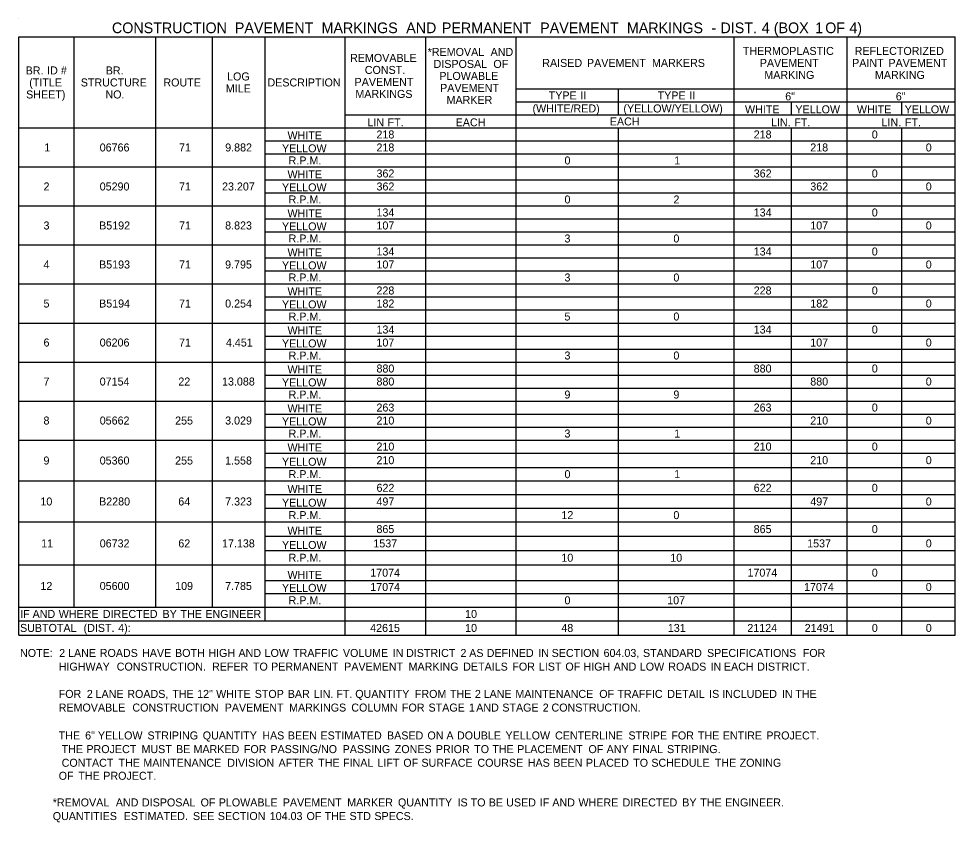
# Model space of a CAD drawing. Extents: x 544420 to 1930787, y -1947044 to 596640.
# Drawn here: x 548031 to 548733, y -1946708 to -1946106 of the extents above; entities that cross this region are included whole.
import ezdxf

# ---------------------------------------------------------------- set-up
doc = ezdxf.new("R2010")
doc.units = 0
doc.layers.add('Default', color=7, linetype='Continuous')

msp = doc.modelspace()

# ---------------------------------------------------------------- linework, layer by layer
at = {"layer": 'Default'}
for p, q in [((548030.53, -1946105.71), (548030.53, -1946105.71)), ((548030.53, -1946119.36), (548732.53, -1946119.36)), ((548030.53, -1946119.36), (548335.71, -1946119.36)), ((548030.53, -1946567.86), (548030.53, -1946119.36)), ((548071.97, -1946546.9), (548071.97, -1946119.36)), ((548133.39, -1946546.9), (548133.39, -1946119.36)), ((548175.81, -1946546.9), (548175.81, -1946119.36)), ((548215.29, -1946557.14), (548215.29, -1946119.36)), ((548275.26, -1946567.86), (548275.26, -1946119.36)), ((548335.71, -1946567.86), (548335.71, -1946119.36)), ((548403.47, -1946567.86), (548403.47, -1946119.36)), ((548566.78, -1946567.86), (548566.78, -1946119.36)), ((548651.61, -1946187.61), (548651.61, -1946119.36)), ((548651.61, -1946567.86), (548651.61, -1946119.36)), ((548732.53, -1946567.86), (548732.53, -1946119.36)), ((548403.47, -1946158.36), (548732.53, -1946158.36)), ((548480.01, -1946177.86), (548480.01, -1946158.36)), ((548403.47, -1946168.11), (548732.53, -1946168.11)), ((548609.68, -1946177.86), (548609.68, -1946168.11)), ((548692.56, -1946177.86), (548692.56, -1946168.11)), ((548275.26, -1946177.86), (548732.53, -1946177.86)), ((548275.26, -1946187.61), (548275.26, -1946177.86)), ((548335.71, -1946187.61), (548335.71, -1946177.86)), ((548403.47, -1946187.61), (548403.47, -1946177.86)), ((548030.53, -1946187.61), (548215.29, -1946187.61)), ((548030.53, -1946187.61), (548175.81, -1946187.61)), ((548175.81, -1946187.61), (548732.53, -1946187.61)), ((548480.01, -1946567.86), (548480.01, -1946187.61)), ((548566.78, -1946187.61), (548651.61, -1946187.61)), ((548609.68, -1946567.86), (548609.68, -1946187.61)), ((548651.61, -1946187.61), (548732.53, -1946187.61)), ((548692.56, -1946567.86), (548692.56, -1946187.61)), ((548215.29, -1946197.36), (548732.53, -1946197.36)), ((548215.29, -1946207.11), (548732.53, -1946207.11)), ((548030.53, -1946216.86), (548732.53, -1946216.86)), ((548215.29, -1946226.61), (548732.53, -1946226.61)), ((548215.29, -1946236.36), (548732.53, -1946236.36)), ((548030.53, -1946246.11), (548732.53, -1946246.11)), ((548215.29, -1946255.86), (548732.53, -1946255.86)), ((548215.29, -1946265.61), (548732.53, -1946265.61)), ((548030.53, -1946275.36), (548732.53, -1946275.36)), ((548215.29, -1946285.11), (548732.53, -1946285.11)), ((548215.29, -1946294.86), (548732.53, -1946294.86)), ((548030.53, -1946304.61), (548732.53, -1946304.61)), ((548215.29, -1946314.36), (548732.53, -1946314.36)), ((548215.29, -1946324.11), (548732.53, -1946324.11)), ((548030.53, -1946333.86), (548732.53, -1946333.86)), ((548215.29, -1946343.61), (548732.53, -1946343.61)), ((548215.29, -1946353.36), (548732.53, -1946353.36)), ((548030.53, -1946363.11), (548732.53, -1946363.11)), ((548215.29, -1946372.86), (548732.53, -1946372.86)), ((548215.29, -1946382.61), (548732.53, -1946382.61)), ((548030.53, -1946392.36), (548732.53, -1946392.36)), ((548215.29, -1946402.11), (548732.53, -1946402.11)), ((548215.29, -1946411.86), (548732.53, -1946411.86)), ((548030.53, -1946421.61), (548732.53, -1946421.61)), ((548215.29, -1946431.36), (548732.53, -1946431.36)), ((548215.29, -1946442.09), (548732.53, -1946442.09)), ((548030.53, -1946452.32), (548732.53, -1946452.32)), ((548215.29, -1946462.56), (548732.53, -1946462.56)), ((548215.29, -1946472.8), (548732.53, -1946472.8)), ((548030.53, -1946483.04), (548732.53, -1946483.04)), ((548215.29, -1946493.76), (548732.53, -1946493.76)), ((548215.29, -1946504.49), (548732.53, -1946504.49)), ((548030.53, -1946515.21), (548732.53, -1946515.21)), ((548215.29, -1946526.91), (548732.53, -1946526.91)), ((548215.29, -1946536.66), (548732.53, -1946536.66)), ((548030.53, -1946546.9), (548732.53, -1946546.9)), ((548215.29, -1946557.14), (548215.29, -1946546.9)), ((548335.71, -1946567.86), (548335.71, -1946546.9)), ((548403.47, -1946567.86), (548403.47, -1946546.9)), ((548480.01, -1946567.86), (548480.01, -1946546.9)), ((548566.78, -1946567.86), (548566.78, -1946546.9)), ((548609.68, -1946567.86), (548609.68, -1946546.9)), ((548651.61, -1946567.86), (548651.61, -1946546.9)), ((548692.56, -1946567.86), (548692.56, -1946546.9)), ((548030.53, -1946557.14), (548732.53, -1946557.14)), ((548275.26, -1946567.86), (548275.26, -1946557.14)), ((548030.53, -1946567.86), (548732.53, -1946567.86))]:
    msp.add_line(p, q, dxfattribs=at)

# ---------------------------------------------------------------- texts
for s, height, p in [('CONSTRUCTION', 8, (548100.42, -1946116.54)), (' PAVEMENT', 8, (548189.57, -1946116.54)), (' MARKINGS', 8, (548254.56, -1946116.54)), (' AND', 8, (548317.98, -1946116.54)), (' PERMANENT', 8, (548344.74, -1946116.54)), (' PAVEMENT', 8, (548418.42, -1946116.54)), (' MARKINGS', 8, (548483.41, -1946116.54)), (' DIST.', 8, (548553.57, -1946116.54)), (' 4', 8, (548584.47, -1946116.54)), (' (BOX', 8, (548593.53, -1946116.54)), (' 1', 8, (548624.57, -1946116.54)), (' OF', 8, (548632.07, -1946116.54)), (' 4)', 8, (548650.18, -1946116.54)), (' -', 8, (548546.82, -1946116.54)), ('REMOVABLE', 6, (548278.9, -1946138.11)), ('*REMOVAL', 6, (548337.08, -1946133.61)), (' AND', 6, (548382.01, -1946133.61)), ('THERMOPLASTIC', 6, (548573.31, -1946132.86)), ('REFLECTORIZED', 6, (548657.11, -1946132.86)), ('DISPOSAL', 6, (548341.49, -1946142.61)), (' OF', 6, (548384.1, -1946142.61)), ('RAISED', 6, (548422.97, -1946141.86)), (' PAVEMENT', 6, (548454.23, -1946141.86)), (' MARKERS', 6, (548502.97, -1946141.86)), ('PAVEMENT', 6, (548585.99, -1946141.86)), ('PAINT', 6, (548655.21, -1946141.86)), (' PAVEMENT', 6, (548680.19, -1946141.86)), ('BR.', 6, (548035.73, -1946147.49)), (' ID', 6, (548049.59, -1946147.49)), (' #', 6, (548059.88, -1946147.49)), ('BR.', 6, (548095.75, -1946147.49)), ('LOG', 6, (548186.72, -1946151.99)), ('CONST.', 6, (548289.93, -1946147.11)), ('PLOWABLE', 6, (548345.81, -1946151.61)), ('MARKING', 6, (548589.42, -1946150.86)), ('MARKING', 6, (548672.3, -1946150.86)), ('(TITLE', 6, (548038.42, -1946156.49)), ('STRUCTURE', 6, (548077.04, -1946156.49)), ('ROUTE', 6, (548138.97, -1946156.49)), ('DESCRIPTION', 6, (548216.96, -1946156.49)), ('PAVEMENT', 6, (548282.27, -1946156.11)), ('SHEET)', 6, (548036.09, -1946165.49)), ('NO.', 6, (548095.52, -1946165.49)), ('MILE', 6, (548185.74, -1946160.99)), ('MARKINGS', 6, (548282.86, -1946165.11)), ('PAVEMENT', 6, (548346.38, -1946160.61)), ('TYPE', 6, (548427.78, -1946166.24)), (' II', 6, (548449.26, -1946166.24)), ('TYPE', 6, (548509.43, -1946166.24)), (' II', 6, (548530.92, -1946166.24)), ('6"', 6, (548605.08, -1946166.91)), ('6"', 6, (548687.96, -1946166.91)), ('MARKER', 6, (548351.21, -1946169.61)), ('(WHITE/RED)', 6, (548415.65, -1946175.99)), ('(YELLOW/YELLOW)', 6, (548483.79, -1946175.99)), ('WHITE', 6, (548574.93, -1946176.66)), ('YELLOW', 6, (548612.72, -1946176.66)), ('WHITE', 6, (548658.78, -1946176.66)), ('YELLOW', 6, (548694.62, -1946176.66)), ('LIN', 6, (548291.9, -1946186.41)), (' FT.', 6, (548304.74, -1946186.41)), ('EACH', 6, (548358.03, -1946186.41)), ('EACH', 6, (548473.57, -1946185.74)), ('LIN.', 6, (548594.4, -1946186.41)), (' FT.', 6, (548609.66, -1946186.41)), ('LIN.', 6, (548677.28, -1946186.41)), (' FT.', 6, (548692.53, -1946186.41)), ('218', 6, (548298.68, -1946195.49)), ('218', 6, (548581.43, -1946195.49)), ('0', 6, (548669.95, -1946195.49)), ('WHITE', 6, (548231.99, -1946196.16)), ('1', 6, (548049.69, -1946205.24)), ('06766', 6, (548091.22, -1946205.24)), ('71', 6, (548150.71, -1946205.24)), ('9.882', 6, (548185.29, -1946205.24)), ('YELLOW', 6, (548227.85, -1946205.91)), ('218', 6, (548298.68, -1946205.24)), ('218', 6, (548623.84, -1946205.24)), ('0', 6, (548710.41, -1946205.24)), ('R.P.M.', 6, (548232.83, -1946214.99)), ('0', 6, (548439.61, -1946214.99)), ('1', 6, (548521.83, -1946214.99)), ('WHITE', 6, (548231.99, -1946225.41)), ('362', 6, (548298.71, -1946224.74)), ('362', 6, (548581.46, -1946224.74)), ('0', 6, (548669.95, -1946224.74)), ('2', 6, (548049.14, -1946234.49)), ('05290', 6, (548091.23, -1946234.49)), ('71', 6, (548150.71, -1946234.49)), ('23.207', 6, (548182.93, -1946234.49)), ('YELLOW', 6, (548227.85, -1946235.16)), ('362', 6, (548298.71, -1946234.49)), ('362', 6, (548623.88, -1946234.49)), ('0', 6, (548710.41, -1946234.49)), ('R.P.M.', 6, (548232.83, -1946244.24)), ('0', 6, (548439.61, -1946244.24)), ('2', 6, (548521.29, -1946244.24)), ('WHITE', 6, (548231.99, -1946254.66)), ('134', 6, (548298.69, -1946253.99)), ('134', 6, (548581.44, -1946253.99)), ('0', 6, (548669.95, -1946253.99)), ('3', 6, (548049.11, -1946263.74)), ('B5192', 6, (548090.79, -1946263.74)), ('71', 6, (548150.71, -1946263.74)), ('8.823', 6, (548185.26, -1946263.74)), ('YELLOW', 6, (548227.85, -1946264.41)), ('107', 6, (548298.68, -1946263.74)), ('107', 6, (548623.84, -1946263.74)), ('0', 6, (548710.41, -1946263.74)), ('R.P.M.', 6, (548232.83, -1946273.49)), ('3', 6, (548439.6, -1946273.49)), ('0', 6, (548521.26, -1946273.49)), ('WHITE', 6, (548231.99, -1946283.91)), ('134', 6, (548298.69, -1946283.24)), ('134', 6, (548581.44, -1946283.24)), ('0', 6, (548669.95, -1946283.24)), ('4', 6, (548049.12, -1946292.99)), ('B5193', 6, (548090.75, -1946292.99)), ('71', 6, (548150.71, -1946292.99)), ('9.795', 6, (548185.23, -1946292.99)), ('YELLOW', 6, (548227.85, -1946293.66)), ('107', 6, (548298.68, -1946292.99)), ('107', 6, (548623.84, -1946292.99)), ('0', 6, (548710.41, -1946292.99)), ('R.P.M.', 6, (548232.83, -1946302.74)), ('3', 6, (548439.6, -1946302.74)), ('0', 6, (548521.26, -1946302.74)), ('WHITE', 6, (548231.99, -1946313.16)), ('228', 6, (548298.68, -1946312.49)), ('228', 6, (548581.43, -1946312.49)), ('0', 6, (548669.95, -1946312.49)), ('5', 6, (548049.09, -1946322.24)), ('B5194', 6, (548090.77, -1946322.24)), ('71', 6, (548150.71, -1946322.24)), ('0.254', 6, (548185.27, -1946322.24)), ('YELLOW', 6, (548227.85, -1946322.91)), ('182', 6, (548298.71, -1946322.24)), ('182', 6, (548623.88, -1946322.24)), ('0', 6, (548710.41, -1946322.24)), ('R.P.M.', 6, (548232.83, -1946331.99)), ('5', 6, (548439.57, -1946331.99)), ('0', 6, (548521.26, -1946331.99)), ('WHITE', 6, (548231.99, -1946342.41)), ('134', 6, (548298.69, -1946341.74)), ('134', 6, (548581.44, -1946341.74)), ('0', 6, (548669.95, -1946341.74)), ('6', 6, (548049.11, -1946351.49)), ('06206', 6, (548091.22, -1946351.49)), ('71', 6, (548150.71, -1946351.49)), ('4.451', 6, (548185.84, -1946351.49)), ('YELLOW', 6, (548227.85, -1946352.16)), ('107', 6, (548298.68, -1946351.49)), ('107', 6, (548623.84, -1946351.49)), ('0', 6, (548710.41, -1946351.49)), ('R.P.M.', 6, (548232.83, -1946361.24)), ('3', 6, (548439.6, -1946361.24)), ('0', 6, (548521.26, -1946361.24)), ('880', 6, (548298.69, -1946370.99)), ('880', 6, (548581.44, -1946370.99)), ('0', 6, (548669.95, -1946370.99)), ('WHITE', 6, (548231.99, -1946371.66)), ('7', 6, (548049.11, -1946380.74)), ('07154', 6, (548091.23, -1946380.74)), ('22', 6, (548150.16, -1946380.74)), ('13.088', 6, (548182.92, -1946380.74)), ('YELLOW', 6, (548227.85, -1946381.41)), ('880', 6, (548298.69, -1946380.74)), ('880', 6, (548623.85, -1946380.74)), ('0', 6, (548710.41, -1946380.74)), ('R.P.M.', 6, (548232.83, -1946390.49)), ('9', 6, (548439.59, -1946390.49)), ('9', 6, (548521.25, -1946390.49)), ('WHITE', 6, (548231.99, -1946400.91)), ('263', 6, (548298.68, -1946400.24)), ('263', 6, (548581.43, -1946400.24)), ('0', 6, (548669.95, -1946400.24)), ('8', 6, (548049.1, -1946409.99)), ('05662', 6, (548091.25, -1946409.99)), ('255', 6, (548147.78, -1946409.99)), ('3.029', 6, (548185.25, -1946409.99)), ('YELLOW', 6, (548227.85, -1946410.66)), ('210', 6, (548298.69, -1946409.99)), ('210', 6, (548623.85, -1946409.99)), ('0', 6, (548710.41, -1946409.99)), ('R.P.M.', 6, (548232.83, -1946419.74)), ('3', 6, (548439.6, -1946419.74)), ('1', 6, (548521.83, -1946419.74)), ('WHITE', 6, (548231.99, -1946430.16)), ('210', 6, (548298.69, -1946429.49)), ('210', 6, (548581.44, -1946429.49)), ('0', 6, (548669.95, -1946429.49)), ('9', 6, (548049.1, -1946439.97)), ('05360', 6, (548091.23, -1946439.97)), ('255', 6, (548147.78, -1946439.97)), ('1.558', 6, (548185.25, -1946439.97)), ('YELLOW', 6, (548227.85, -1946440.89)), ('210', 6, (548298.69, -1946439.72)), ('210', 6, (548623.85, -1946439.72)), ('0', 6, (548710.41, -1946439.72)), ('R.P.M.', 6, (548232.83, -1946450.2)), ('0', 6, (548439.61, -1946450.2)), ('1', 6, (548521.83, -1946450.2)), ('WHITE', 6, (548231.99, -1946461.36)), ('622', 6, (548298.71, -1946460.44)), ('622', 6, (548581.46, -1946460.44)), ('0', 6, (548669.95, -1946460.44)), ('10', 6, (548046.79, -1946470.68)), ('B2280', 6, (548090.77, -1946470.68)), ('64', 6, (548150.14, -1946470.68)), ('7.323', 6, (548185.26, -1946470.68)), ('YELLOW', 6, (548227.85, -1946471.6)), ('497', 6, (548298.68, -1946470.68)), ('497', 6, (548623.84, -1946470.68)), ('0', 6, (548710.41, -1946470.68)), ('R.P.M.', 6, (548232.83, -1946480.92)), ('12', 6, (548437.3, -1946480.92)), ('0', 6, (548521.26, -1946480.92)), ('WHITE', 6, (548231.99, -1946492.56)), ('865', 6, (548298.66, -1946491.4)), ('865', 6, (548581.41, -1946491.4)), ('0', 6, (548669.95, -1946491.4)), ('11', 6, (548047.36, -1946502.12)), ('06732', 6, (548091.25, -1946502.12)), ('62', 6, (548150.16, -1946502.12)), ('17.138', 6, (548182.92, -1946502.12)), ('YELLOW', 6, (548227.85, -1946503.29)), ('1537', 6, (548296.35, -1946502.12)), ('1537', 6, (548621.51, -1946502.12)), ('0', 6, (548710.41, -1946502.12)), ('R.P.M.', 6, (548232.83, -1946512.85)), ('10', 6, (548437.28, -1946512.85)), ('10', 6, (548518.93, -1946512.85)), ('17074', 6, (548294.03, -1946524.06)), ('17074', 6, (548576.78, -1946524.06)), ('0', 6, (548669.95, -1946524.06)), ('WHITE', 6, (548231.99, -1946525.71)), ('12', 6, (548046.81, -1946534.05)), ('05600', 6, (548091.23, -1946534.05)), ('109', 6, (548147.79, -1946534.05)), ('7.785', 6, (548185.23, -1946534.05)), ('YELLOW', 6, (548227.85, -1946535.46)), ('17074', 6, (548294.03, -1946534.79)), ('17074', 6, (548619.2, -1946534.79)), ('0', 6, (548710.41, -1946534.79)), ('R.P.M.', 6, (548232.83, -1946544.78)), ('0', 6, (548439.61, -1946544.78)), ('107', 6, (548516.59, -1946544.78)), ('IF', 6, (548031.62, -1946555.02)), (' AND', 6, (548038.69, -1946555.02)), (' WHERE', 6, (548058.27, -1946555.02)), (' DIRECTED', 6, (548091.36, -1946555.02)), (' BY', 6, (548136.09, -1946555.02)), (' THE', 6, (548149.54, -1946555.02)), (' ENGINEER', 6, (548168.19, -1946555.02)), ('10', 6, (548365.13, -1946555.02)), ('SUBTOTAL', 6, (548031.51, -1946565.5)), (' (DIST.', 6, (548076.9, -1946565.5)), (' 4):', 6, (548102.87, -1946565.5)), ('42615', 6, (548293.96, -1946565.5)), ('10', 6, (548365.13, -1946565.5)), ('48', 6, (548437.26, -1946565.5)), ('131', 6, (548517.08, -1946565.5)), ('21124', 6, (548576.68, -1946565.5)), ('21491', 6, (548619.67, -1946565.5)), ('0', 6, (548669.96, -1946565.5)), ('0', 6, (548710.42, -1946565.5)), ('NOTE:', 6, (548031.51, -1946584.27)), ('  2', 6, (548056.39, -1946584.27)), (' LANE', 6, (548065.27, -1946584.27)), (' ROADS', 6, (548089.05, -1946584.27)), (' HAVE', 6, (548120.75, -1946584.27)), (' BOTH', 6, (548145.46, -1946584.27)), (' HIGH', 6, (548170.41, -1946584.27)), (' AND', 6, (548193.02, -1946584.27)), (' LOW', 6, (548212.6, -1946584.27)), (' TRAFFIC', 6, (548233.92, -1946584.27)), (' VOLUME', 6, (548271.31, -1946584.27)), (' IN', 6, (548308.6, -1946584.27)), (' DISTRICT', 6, (548318.62, -1946584.27)), (' 2', 6, (548359.44, -1946584.27)), (' AS', 6, (548365.98, -1946584.27)), (' DEFINED', 6, (548379.06, -1946584.27)), (' IN', 6, (548417.74, -1946584.27)), (' SECTION', 6, (548427.76, -1946584.27)), (' 604.03,', 6, (548466.67, -1946584.27)), (' STANDARD', 6, (548496.21, -1946584.27)), (' SPECIFICATIONS', 6, (548544.21, -1946584.27)), (' FOR', 6, (548615.98, -1946584.27)), ('             HIGHWAY', 6, (548031.51, -1946594.5)), (' CONSTRUCTION.', 6, (548101.76, -1946594.5)), (' REFER', 6, (548173.22, -1946594.5)), (' TO', 6, (548203.85, -1946594.5)), (' PERMANENT', 6, (548217.45, -1946594.5)), (' PAVEMENT', 6, (548272.25, -1946594.5)), (' MARKING', 6, (548320.53, -1946594.5)), (' DETAILS', 6, (548361.46, -1946594.5)), (' FOR', 6, (548398.29, -1946594.5)), (' LIST', 6, (548418.2, -1946594.5)), (' OF', 6, (548438.07, -1946594.5)), (' HIGH', 6, (548451.65, -1946594.5)), (' AND', 6, (548474.26, -1946594.5)), (' LOW', 6, (548493.84, -1946594.5)), (' ROADS', 6, (548515.17, -1946594.5)), (' IN', 6, (548546.87, -1946594.5)), (' EACH', 6, (548556.9, -1946594.5)), (' DISTRICT.', 6, (548581.85, -1946594.5)), ('             FOR', 6, (548031.51, -1946614.98)), (' 2', 6, (548079.35, -1946614.98)), (' LANE', 6, (548085.89, -1946614.98)), (' ROADS,', 6, (548109.68, -1946614.98)), (' THE', 6, (548143.4, -1946614.98)), (' 12"', 6, (548162.05, -1946614.98)), (' WHITE', 6, (548176.28, -1946614.98)), (' STOP', 6, (548205.17, -1946614.98)), (' BAR', 6, (548229.96, -1946614.98)), (' LIN.', 6, (548249.42, -1946614.98)), (' FT.', 6, (548266.38, -1946614.98)), (' QUANTITY', 6, (548280.55, -1946614.98)), (' FROM', 6, (548325.2, -1946614.98)), (' THE', 6, (548351.58, -1946614.98)), (' 2', 6, (548370.23, -1946614.98)), (' LANE', 6, (548376.78, -1946614.98)), (' MAINTENANCE', 6, (548400.56, -1946614.98)), (' OF', 6, (548463.46, -1946614.98)), (' TRAFFIC', 6, (548477.05, -1946614.98)), (' DETAIL', 6, (548514.44, -1946614.98)), (' IS', 6, (548545.82, -1946614.98)), (' INCLUDED', 6, (548555.63, -1946614.98)), (' IN', 6, (548600.36, -1946614.98)), (' THE', 6, (548610.39, -1946614.98)), ('             REMOVABLE', 6, (548031.51, -1946625.22)), (' CONSTRUCTION', 6, (548113.5, -1946625.22)), (' PAVEMENT', 6, (548182.68, -1946625.22)), (' MARKINGS', 6, (548230.96, -1946625.22)), (' COLUMN', 6, (548277.57, -1946625.22)), (' FOR', 6, (548315.55, -1946625.22)), (' STAGE', 6, (548335.46, -1946625.22)), (' 1', 6, (548365.76, -1946625.22)), (' AND', 6, (548371.21, -1946625.22)), (' STAGE', 6, (548390.79, -1946625.22)), (' 2', 6, (548421.09, -1946625.22)), (' CONSTRUCTION.', 6, (548427.63, -1946625.22)), ('             THE', 6, (548031.51, -1946646.12)), (' 6"', 6, (548078.09, -1946646.12)), (' YELLOW', 6, (548087.66, -1946646.12)), (' STRIPING', 6, (548124.83, -1946646.12)), (' QUANTITY', 6, (548166.23, -1946646.12)), (' HAS', 6, (548210.88, -1946646.12)), (' BEEN', 6, (548230.01, -1946646.12)), (' ESTIMATED', 6, (548254.48, -1946646.12)), (' BASED', 6, (548304.35, -1946646.12)), (' ON', 6, (548334.65, -1946646.12)), (' A', 6, (548348.87, -1946646.12)), (' DOUBLE', 6, (548356.8, -1946646.12)), (' YELLOW', 6, (548393.16, -1946646.12)), (' CENTERLINE', 6, (548430.33, -1946646.12)), (' STRIPE', 6, (548485.32, -1946646.12)), (' FOR', 6, (548517.48, -1946646.12)), (' THE', 6, (548537.39, -1946646.12)), (' ENTIRE', 6, (548556.04, -1946646.12)), (' PROJECT.', 6, (548588.67, -1946646.12)), ('THE', 6, (548062.71, -1946656.36)), (' PROJECT', 6, (548079.03, -1946656.36)), (' MUST', 6, (548120.32, -1946656.36)), (' BE', 6, (548146.23, -1946656.36)), (' MARKED', 6, (548159.3, -1946656.36)), (' FOR', 6, (548197.05, -1946656.36)), (' PASSING/NO', 6, (548216.96, -1946656.36)), (' PASSING', 6, (548271.09, -1946656.36)), (' ZONES', 6, (548310.17, -1946656.36)), (' PRIOR', 6, (548340.94, -1946656.36)), (' TO', 6, (548369.71, -1946656.36)), (' THE', 6, (548383.3, -1946656.36)), (' PLACEMENT', 6, (548401.95, -1946656.36)), (' OF', 6, (548455.36, -1946656.36)), (' ANY', 6, (548468.95, -1946656.36)), (' FINAL', 6, (548488.45, -1946656.36)), (' STRIPING.', 6, (548514.24, -1946656.36)), ('CONTACT', 6, (548062.71, -1946666.6)), (' THE', 6, (548103.06, -1946666.6)), (' MAINTENANCE', 6, (548121.71, -1946666.6)), (' DIVISION', 6, (548184.61, -1946666.6)), (' AFTER', 6, (548223.06, -1946666.6)), (' THE', 6, (548252.75, -1946666.6)), (' FINAL', 6, (548271.4, -1946666.6)), (' LIFT', 6, (548297.19, -1946666.6)), (' OF', 6, (548316.58, -1946666.6)), (' SURFACE', 6, (548330.17, -1946666.6)), (' COURSE', 6, (548372.11, -1946666.6)), (' HAS', 6, (548409.86, -1946666.6)), (' BEEN', 6, (548428.99, -1946666.6)), (' PLACED', 6, (548453.47, -1946666.6)), (' TO', 6, (548488.9, -1946666.6)), (' SCHEDULE', 6, (548502.49, -1946666.6)), (' THE', 6, (548550.03, -1946666.6)), (' ZONING', 6, (548568.68, -1946666.6)), ('             OF', 6, (548031.51, -1946676.35)), (' THE', 6, (548073.03, -1946676.35)), (' PROJECT.', 6, (548091.68, -1946676.35)), ('           *REMOVAL', 6, (548031.51, -1946696.34)), (' AND', 6, (548101.07, -1946696.34)), (' DISPOSAL', 6, (548120.66, -1946696.34)), (' OF', 6, (548164.62, -1946696.34)), (' PLOWABLE', 6, (548178.21, -1946696.34)), (' PAVEMENT', 6, (548226.21, -1946696.34)), (' MARKER', 6, (548274.5, -1946696.34)), (' QUANTITY', 6, (548312.58, -1946696.34)), (' IS', 6, (548357.23, -1946696.34)), (' TO', 6, (548367.04, -1946696.34)), (' BE', 6, (548380.64, -1946696.34)), (' USED', 6, (548393.71, -1946696.34)), (' IF', 6, (548418.88, -1946696.34)), (' AND', 6, (548428.27, -1946696.34)), (' WHERE', 6, (548447.86, -1946696.34)), (' DIRECTED', 6, (548480.94, -1946696.34)), (' BY', 6, (548525.68, -1946696.34)), (' THE', 6, (548539.13, -1946696.34)), (' ENGINEER.', 6, (548557.78, -1946696.34)), ('           QUANTITIES', 6, (548031.51, -1946706.57)), (' ESTIMATED.', 6, (548106.98, -1946706.57)), (' SEE', 6, (548158.89, -1946706.57)), (' SECTION', 6, (548177.55, -1946706.57)), (' 104.03', 6, (548216.45, -1946706.57)), (' OF', 6, (548244.03, -1946706.57)), (' THE', 6, (548257.62, -1946706.57)), (' STD', 6, (548276.27, -1946706.57)), (' SPECS.', 6, (548294.92, -1946706.57))]:
    msp.add_text(s, height=height, dxfattribs=at).set_placement(p)

doc.saveas('drawing.dxf')
